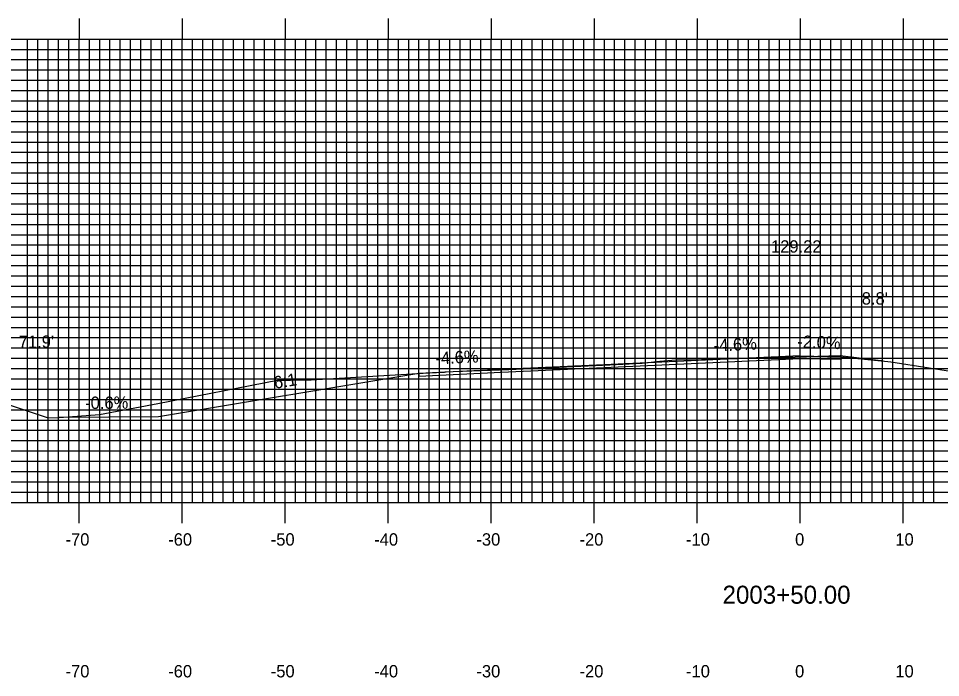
# Model space of a CAD drawing. Extents: x 851533 to 851876, y 366605 to 366825.
# Drawn here: x 851622.6 to 851712.1, y 366671 to 366735.1 of the extents above; entities that cross this region are included whole.
import ezdxf

# ---------------------------------------------------------------- set-up
doc = ezdxf.new("R2010")
doc.units = 0
for name, color, linetype in [('ANNOTATION', 7, 'Continuous'), ('D_Roadway_Centerline', 7, 'Continuous'), ('D_Roadway_Centerline_Text', 7, 'Continuous'), ('D_Roadway_Edge_Shoulder', 7, 'Continuous'), ('D_Roadway_Edge_TW', 7, 'Continuous'), ('D_Roadway_SlopeLines', 7, 'Continuous'), ('D_Text_Standard', 7, 'Continuous'), ('H_V ANNOTATION', 7, 'Continuous'), ('M_Roadway_Centerline', 7, 'Continuous'), ('MAJOR', 7, 'Continuous'), ('MINOR', 7, 'Continuous'), ('S_Roadway_Centerline', 7, 'Continuous')]:
    doc.layers.add(name, color=color, linetype=linetype)

msp = doc.modelspace()

# ---------------------------------------------------------------- linework, layer by layer
at = {"layer": 'D_Roadway_Centerline'}
for p, q in [((851698.452, 366702.28), (851702.452, 366702.2)), ((851698.452, 366702.03), (851702.452, 366701.95))]:
    msp.add_line(p, q, dxfattribs=at)
at = {"layer": 'D_Roadway_Edge_Shoulder'}
for points in [[(851698.452, 366702.28), (851702.452, 366702.2), (851702.452, 366701.95), (851698.452, 366702.03)], [(851669.432, 366700.946), (851661.432, 366700.578), (851661.432, 366700.328), (851669.432, 366700.696)]]:
    msp.add_lwpolyline(points, close=True, dxfattribs=at)
at = {"layer": 'D_Roadway_Edge_TW'}
for points in [[(851698.452, 366702.28), (851686.451, 366701.728), (851686.451, 366701.478), (851698.452, 366702.03)], [(851686.451, 366701.728), (851674.451, 366701.176), (851674.451, 366700.926), (851686.451, 366701.478)], [(851674.451, 366701.176), (851669.432, 366700.946), (851669.432, 366700.696), (851674.451, 366700.926)]]:
    msp.add_lwpolyline(points, close=True, dxfattribs=at)
msp.add_lwpolyline([(851674.451, 366700.926), (851674.451, 366701.176)], dxfattribs=at)
at = {"layer": 'D_Roadway_SlopeLines'}
msp.add_line((851702.452, 366702.2), (851706.971, 366701.734), dxfattribs=at)
for points in [[(851661.432, 366700.578), (851636.153, 366696.364)], [(851636.153, 366696.364), (851626.526, 366696.307)]]:
    msp.add_lwpolyline(points, dxfattribs=at)
at = {"layer": 'MAJOR'}
for p, q in [((851628.452, 366735.059), (851628.452, 366733.055)), ((851638.452, 366735.059), (851638.452, 366733.055)), ((851648.452, 366735.059), (851648.452, 366733.055)), ((851658.452, 366735.059), (851658.452, 366733.055)), ((851668.452, 366735.059), (851668.452, 366733.055)), ((851678.452, 366735.059), (851678.452, 366733.055)), ((851688.452, 366735.059), (851688.452, 366733.055)), ((851698.452, 366735.059), (851698.452, 366733.055)), ((851708.452, 366735.059), (851708.452, 366733.055)), ((851558.452, 366733.055), (851838.452, 366733.055)), ((851558.452, 366733.055), (851838.452, 366733.055)), ((851628.452, 366688.055), (851628.452, 366733.055)), ((851638.452, 366688.055), (851638.452, 366733.055)), ((851648.452, 366688.055), (851648.452, 366733.055)), ((851658.452, 366688.055), (851658.452, 366733.055)), ((851668.452, 366688.055), (851668.452, 366733.055)), ((851678.452, 366688.055), (851678.452, 366733.055)), ((851688.452, 366688.055), (851688.452, 366733.055)), ((851698.452, 366688.055), (851698.452, 366733.055)), ((851708.452, 366688.055), (851708.452, 366733.055)), ((851558.452, 366728.055), (851838.452, 366728.055)), ((851558.452, 366723.055), (851838.452, 366723.055)), ((851558.452, 366718.055), (851838.452, 366718.055)), ((851558.452, 366713.055), (851838.452, 366713.055)), ((851558.452, 366708.055), (851838.452, 366708.055)), ((851558.452, 366703.055), (851838.452, 366703.055)), ((851558.452, 366698.055), (851838.452, 366698.055)), ((851558.452, 366693.055), (851838.452, 366693.055)), ((851558.452, 366688.055), (851838.452, 366688.055)), ((851558.452, 366688.055), (851838.452, 366688.055)), ((851628.452, 366686.051), (851628.452, 366688.055)), ((851638.452, 366686.051), (851638.452, 366688.055)), ((851648.452, 366686.051), (851648.452, 366688.055)), ((851658.452, 366686.051), (851658.452, 366688.055)), ((851668.452, 366686.051), (851668.452, 366688.055)), ((851678.452, 366686.051), (851678.452, 366688.055)), ((851688.452, 366686.051), (851688.452, 366688.055)), ((851698.452, 366686.051), (851698.452, 366688.055)), ((851708.452, 366686.051), (851708.452, 366688.055))]:
    msp.add_line(p, q, dxfattribs=at)
at = {"layer": 'MINOR'}
for p, q in [((851623.452, 366688.055), (851623.452, 366733.055)), ((851624.452, 366688.055), (851624.452, 366733.055)), ((851625.452, 366688.055), (851625.452, 366733.055)), ((851626.452, 366688.055), (851626.452, 366733.055)), ((851627.452, 366688.055), (851627.452, 366733.055)), ((851629.452, 366688.055), (851629.452, 366733.055)), ((851630.452, 366688.055), (851630.452, 366733.055)), ((851631.452, 366688.055), (851631.452, 366733.055)), ((851632.452, 366688.055), (851632.452, 366733.055)), ((851633.452, 366688.055), (851633.452, 366733.055)), ((851634.452, 366688.055), (851634.452, 366733.055)), ((851635.452, 366688.055), (851635.452, 366733.055)), ((851636.452, 366688.055), (851636.452, 366733.055)), ((851637.452, 366688.055), (851637.452, 366733.055)), ((851639.452, 366688.055), (851639.452, 366733.055)), ((851640.452, 366688.055), (851640.452, 366733.055)), ((851641.452, 366688.055), (851641.452, 366733.055)), ((851642.452, 366688.055), (851642.452, 366733.055)), ((851643.452, 366688.055), (851643.452, 366733.055)), ((851644.452, 366688.055), (851644.452, 366733.055)), ((851645.452, 366688.055), (851645.452, 366733.055)), ((851646.452, 366688.055), (851646.452, 366733.055)), ((851647.452, 366688.055), (851647.452, 366733.055)), ((851649.452, 366688.055), (851649.452, 366733.055)), ((851650.452, 366688.055), (851650.452, 366733.055)), ((851651.452, 366688.055), (851651.452, 366733.055)), ((851652.452, 366688.055), (851652.452, 366733.055)), ((851653.452, 366688.055), (851653.452, 366733.055)), ((851654.452, 366688.055), (851654.452, 366733.055)), ((851655.452, 366688.055), (851655.452, 366733.055)), ((851656.452, 366688.055), (851656.452, 366733.055)), ((851657.452, 366688.055), (851657.452, 366733.055)), ((851659.452, 366688.055), (851659.452, 366733.055)), ((851660.452, 366688.055), (851660.452, 366733.055)), ((851661.452, 366688.055), (851661.452, 366733.055)), ((851662.452, 366688.055), (851662.452, 366733.055)), ((851663.452, 366688.055), (851663.452, 366733.055)), ((851664.452, 366688.055), (851664.452, 366733.055)), ((851665.452, 366688.055), (851665.452, 366733.055)), ((851666.452, 366688.055), (851666.452, 366733.055)), ((851667.452, 366688.055), (851667.452, 366733.055)), ((851669.452, 366688.055), (851669.452, 366733.055)), ((851670.452, 366688.055), (851670.452, 366733.055)), ((851671.452, 366688.055), (851671.452, 366733.055)), ((851672.452, 366688.055), (851672.452, 366733.055)), ((851673.452, 366688.055), (851673.452, 366733.055)), ((851674.452, 366688.055), (851674.452, 366733.055)), ((851675.452, 366688.055), (851675.452, 366733.055)), ((851676.452, 366688.055), (851676.452, 366733.055)), ((851677.452, 366688.055), (851677.452, 366733.055)), ((851679.452, 366688.055), (851679.452, 366733.055)), ((851680.452, 366688.055), (851680.452, 366733.055)), ((851681.452, 366688.055), (851681.452, 366733.055)), ((851682.452, 366688.055), (851682.452, 366733.055)), ((851683.452, 366688.055), (851683.452, 366733.055)), ((851684.452, 366688.055), (851684.452, 366733.055)), ((851685.452, 366688.055), (851685.452, 366733.055)), ((851686.452, 366688.055), (851686.452, 366733.055)), ((851687.452, 366688.055), (851687.452, 366733.055)), ((851689.452, 366688.055), (851689.452, 366733.055)), ((851690.452, 366688.055), (851690.452, 366733.055)), ((851691.452, 366688.055), (851691.452, 366733.055)), ((851692.452, 366688.055), (851692.452, 366733.055)), ((851693.452, 366688.055), (851693.452, 366733.055)), ((851694.452, 366688.055), (851694.452, 366733.055)), ((851695.452, 366688.055), (851695.452, 366733.055)), ((851696.452, 366688.055), (851696.452, 366733.055)), ((851697.452, 366688.055), (851697.452, 366733.055)), ((851699.452, 366688.055), (851699.452, 366733.055)), ((851700.452, 366688.055), (851700.452, 366733.055)), ((851701.452, 366688.055), (851701.452, 366733.055)), ((851702.452, 366688.055), (851702.452, 366733.055)), ((851703.452, 366688.055), (851703.452, 366733.055)), ((851704.452, 366688.055), (851704.452, 366733.055)), ((851705.452, 366688.055), (851705.452, 366733.055)), ((851706.452, 366688.055), (851706.452, 366733.055)), ((851707.452, 366688.055), (851707.452, 366733.055)), ((851709.452, 366688.055), (851709.452, 366733.055)), ((851710.452, 366688.055), (851710.452, 366733.055)), ((851711.452, 366688.055), (851711.452, 366733.055)), ((851558.452, 366732.055), (851838.452, 366732.055)), ((851558.452, 366731.055), (851838.452, 366731.055)), ((851558.452, 366730.055), (851838.452, 366730.055)), ((851558.452, 366729.055), (851838.452, 366729.055)), ((851558.452, 366727.055), (851838.452, 366727.055)), ((851558.452, 366726.055), (851838.452, 366726.055)), ((851558.452, 366725.055), (851838.452, 366725.055)), ((851558.452, 366724.055), (851838.452, 366724.055)), ((851558.452, 366722.055), (851838.452, 366722.055)), ((851558.452, 366721.055), (851838.452, 366721.055)), ((851558.452, 366720.055), (851838.452, 366720.055)), ((851558.452, 366719.055), (851838.452, 366719.055)), ((851558.452, 366717.055), (851838.452, 366717.055)), ((851558.452, 366716.055), (851838.452, 366716.055)), ((851558.452, 366715.055), (851838.452, 366715.055)), ((851558.452, 366714.055), (851838.452, 366714.055)), ((851558.452, 366712.055), (851838.452, 366712.055)), ((851558.452, 366711.055), (851838.452, 366711.055)), ((851558.452, 366710.055), (851838.452, 366710.055)), ((851558.452, 366709.055), (851838.452, 366709.055)), ((851558.452, 366707.055), (851838.452, 366707.055)), ((851558.452, 366706.055), (851838.452, 366706.055)), ((851558.452, 366705.055), (851838.452, 366705.055)), ((851558.452, 366704.055), (851838.452, 366704.055)), ((851558.452, 366702.055), (851838.452, 366702.055)), ((851558.452, 366701.055), (851838.452, 366701.055)), ((851558.452, 366700.055), (851838.452, 366700.055)), ((851558.452, 366699.055), (851838.452, 366699.055)), ((851558.452, 366697.055), (851838.452, 366697.055)), ((851558.452, 366696.055), (851838.452, 366696.055)), ((851558.452, 366695.055), (851838.452, 366695.055)), ((851558.452, 366694.055), (851838.452, 366694.055)), ((851558.452, 366692.055), (851838.452, 366692.055)), ((851558.452, 366691.055), (851838.452, 366691.055)), ((851558.452, 366690.055), (851838.452, 366690.055)), ((851558.452, 366689.055), (851838.452, 366689.055))]:
    msp.add_line(p, q, dxfattribs=at)
at = {"layer": 'S_Roadway_Centerline'}
msp.add_lwpolyline([(851614.519, 366699.892), (851625.463, 366696.27), (851626.525, 366696.307), (851630.447, 366696.596), (851636.103, 366697.647), (851647.732, 366699.911), (851648.972, 366699.935), (851650.543, 366699.968), (851650.996, 366699.97), (851661.868, 366700.618), (851663.14, 366700.679), (851663.933, 366700.716), (851663.994, 366700.723), (851664.758, 366700.754), (851670.17, 366700.972), (851679.982, 366701.422), (851683.139, 366701.587), (851684.841, 366701.786), (851686.399, 366701.904), (851688.87, 366701.925), (851695.824, 366702.118), (851702.353, 366702.319), (851706.295, 366701.835), (851706.388, 366701.823), (851706.662, 366701.777), (851707.28, 366701.69), (851725.864, 366698.778)], dxfattribs=at)

# ---------------------------------------------------------------- texts
at = {"layer": 'ANNOTATION'}
for s, rotation, p in [('-4.6%', 2.63357, (851690.094, 366702.698)), ('-2.0%', 357.70983, (851698.174, 366703.093)), ('-4.6%', 2.63384, (851663.073, 366701.456)), ('6:1', 9.46413, (851647.46, 366699.077)), ('-0.6%', 0.33927, (851629.039, 366697.122))]:
    msp.add_text(s, height=1.2, rotation=rotation, dxfattribs=at).set_placement(p)
at = {"layer": 'D_Roadway_Centerline_Text'}
msp.add_text('129.22', height=1.2, dxfattribs=at).set_placement((851695.632, 366712.31))
at = {"layer": 'D_Text_Standard'}
for s, p in [("8.8'", (851704.443, 366707.268)), ("71.9'", (851622.592, 366703.062))]:
    msp.add_text(s, height=1.2, dxfattribs=at).set_placement(p)
at = {"layer": 'H_V ANNOTATION'}
for s, height, p in [('-70', 1.2, (851627.135, 366683.855)), ('-60', 1.2, (851637.103, 366683.855)), ('-50', 1.2, (851647.06, 366683.855)), ('-40', 1.2, (851657.103, 366683.855)), ('-30', 1.2, (851667.028, 366683.855)), ('-20', 1.2, (851677.039, 366683.855)), ('-10', 1.2, (851687.381, 366683.855)), ('0', 1.2, (851697.97, 366683.855)), ('10', 1.2, (851707.702, 366683.855)), ('2003+50.00', 1.75, (851690.929, 366678.211)), ('-70', 1.2, (851627.135, 366671.055)), ('-60', 1.2, (851637.103, 366671.055)), ('-50', 1.2, (851647.06, 366671.055)), ('-40', 1.2, (851657.103, 366671.055)), ('-30', 1.2, (851667.028, 366671.055)), ('-20', 1.2, (851677.039, 366671.055)), ('-10', 1.2, (851687.381, 366671.055)), ('0', 1.2, (851697.97, 366671.055)), ('10', 1.2, (851707.702, 366671.055))]:
    msp.add_text(s, height=height, dxfattribs=at).set_placement(p)
at = {"layer": 'M_Roadway_Centerline'}
for s, p in [('C', (851686.394, 366701.904)), ('L', (851686.399, 366701.897)), ('C', (851663.989, 366700.723)), ('L', (851663.994, 366700.715))]:
    msp.add_text(s, height=0.0146, dxfattribs=at).set_placement(p)

doc.saveas('drawing.dxf')
